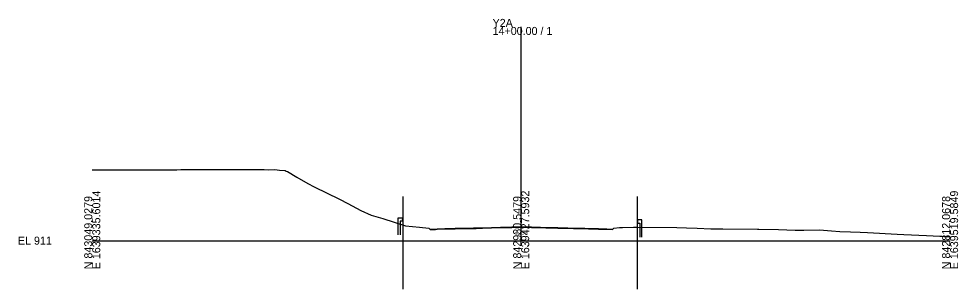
# Model space of a CAD drawing. Extents: x -26 to 303, y -10 to 10517.
# Drawn here: x -25.7 to 302.8, y 3483.1 to 3577.5 of the extents above; entities that cross this region are included whole.
import ezdxf

# ---------------------------------------------------------------- set-up
doc = ezdxf.new("R2010")
doc.units = 0
for name, color, linetype in [('Exist Cross Section Cell', 7, 'Continuous'), ('Exist XS Center Line Elevation Label', 7, 'Continuous'), ('Exist XS Ground Line', 7, 'Continuous'), ('Prop CMT Guardrail Widen Shoulder', 7, 'Continuous'), ('Prop CMT Pvmt Surface Overlay', 7, 'Continuous'), ('Scratch_Level_0', 7, 'Continuous')]:
    doc.layers.add(name, color=color, linetype=linetype)

msp = doc.modelspace()

# ---------------------------------------------------------------- linework, layer by layer
at = {"layer": 'Exist Cross Section Cell'}
for p, q in [((150, 3500), (150, 3574.66)), ((0, 3500), (150, 3500)), ((150, 3500), (300, 3500))]:
    msp.add_line(p, q, dxfattribs=at)
at = {"layer": 'Exist XS Ground Line'}
msp.add_lwpolyline([(0, 3524.72), (0.35, 3524.72), (0.66, 3524.72), (1.06, 3524.73), (2.44, 3524.73), (3.52, 3524.74), (4.22, 3524.74), (5.13, 3524.75), (6.01, 3524.75), (6.68, 3524.76), (7.61, 3524.75), (9.21, 3524.76), (9.85, 3524.76), (10.4, 3524.76), (10.81, 3524.77), (11.86, 3524.77), (13.29, 3524.77), (14.67, 3524.78), (16.18, 3524.78), (17.36, 3524.78), (19.34, 3524.79), (20.26, 3524.78), (21.44, 3524.79), (22.04, 3524.79), (22.51, 3524.79), (25.67, 3524.79), (26.22, 3524.79), (28.84, 3524.8), (29.17, 3524.8), (29.59, 3524.8), (30.95, 3524.81), (32, 3524.81), (32.95, 3524.82), (33.67, 3524.82), (35.17, 3524.82), (35.89, 3524.82), (36.72, 3524.83), (38.08, 3524.84), (38.39, 3524.84), (40.37, 3524.84), (41.5, 3524.84), (41.82, 3524.84), (44.66, 3524.83), (45.9, 3524.82), (47.83, 3524.82), (48.77, 3524.83), (49.97, 3524.81), (50.55, 3524.81), (50.99, 3524.81), (52.13, 3524.87), (54.24, 3524.85), (54.62, 3524.89), (56.85, 3524.87), (57.42, 3524.84), (60.07, 3524.85), (61.49, 3524.74), (63.8, 3524.83), (65.44, 3524.61), (67.41, 3524.57), (67.86, 3524.26), (68.27, 3524.13), (71.58, 3522.18), (75.36, 3520), (77.57, 3518.78), (86.5, 3514.55), (89.33, 3513.04), (93.88, 3510.51), (97.49, 3508.94), (101.61, 3507.76), (109.57, 3505.22), (114.47, 3504.67), (117.71, 3504.33), (118.16, 3503.85), (118.65, 3503.88), (120.03, 3503.95), (120.63, 3504), (123.35, 3504.11), (123.79, 3504.13), (125.32, 3504.16), (126.96, 3504.19), (127.43, 3504.2), (128.94, 3504.22), (130.12, 3504.25), (131.8, 3504.28), (132.2, 3504.28), (133.29, 3504.3), (134.29, 3504.31), (135.58, 3504.35), (136.07, 3504.37), (136.45, 3504.38), (139.66, 3504.44), (142.8, 3504.55), (143.73, 3504.57), (144.98, 3504.6), (145.95, 3504.63), (146.76, 3504.66), (147.81, 3504.69), (148.86, 3504.7), (149.36, 3504.7), (150, 3504.7), (152.28, 3504.68), (153.63, 3504.66), (155.44, 3504.62), (155.77, 3504.62), (156.75, 3504.59), (158.61, 3504.53), (159.23, 3504.51), (160.04, 3504.49), (161.77, 3504.44), (162.8, 3504.42), (164.12, 3504.39), (164.58, 3504.38), (164.94, 3504.37), (166.36, 3504.35), (168.28, 3504.3), (169.31, 3504.27), (171.27, 3504.22), (171.7, 3504.21), (172.27, 3504.2), (173.49, 3504.18), (174.43, 3504.14), (175.27, 3504.11), (176.34, 3504.09), (177.05, 3504.07), (177.6, 3504.06), (179.29, 3504.01), (179.97, 3503.97), (181.9, 3503.86), (182.44, 3504.35), (184.42, 3504.55), (184.73, 3504.58), (185.11, 3504.62), (185.44, 3504.63), (189.3, 3504.72), (190.3, 3504.73), (204.4, 3504.62), (207.83, 3504.47), (211.53, 3504.33), (216.29, 3504.19), (218.65, 3504.17), (220.49, 3504.16), (232.59, 3504.07), (233.16, 3504.06), (240.04, 3503.88), (245.82, 3503.68), (247.16, 3503.65), (248.9, 3503.69), (254.29, 3503.79), (258.48, 3503.42), (261.42, 3503.19), (265.21, 3503.05), (268.55, 3503.02), (271.14, 3502.89), (281.51, 3502.33), (283.8, 3502.19), (291.74, 3501.77), (296.46, 3501.54), (297.06, 3501.52), (297.82, 3501.49), (300, 3501.45)], dxfattribs=at)
at = {"layer": 'Prop CMT Guardrail Widen Shoulder'}
for points in [[(107.03, 3502.02), (107.03, 3508.02)], [(107.03, 3508.02), (108.36, 3508.02), (108.63, 3507.72)], [(108.63, 3507.14), (108.36, 3506.85), (107.69, 3506.85)], [(107.69, 3506.85), (107.69, 3502.02)], [(108.63, 3507.72), (108.36, 3507.43)], [(108.36, 3507.43), (108.63, 3507.14)], [(192.14, 3507.23), (190.81, 3507.23), (190.54, 3506.94)], [(190.54, 3506.94), (190.81, 3506.65)], [(190.81, 3506.65), (190.54, 3506.36)], [(190.54, 3506.36), (190.81, 3506.07), (191.48, 3506.07)], [(191.48, 3506.07), (191.48, 3501.23)], [(192.14, 3501.23), (192.14, 3507.23)]]:
    msp.add_lwpolyline(points, dxfattribs=at)
at = {"layer": 'Prop CMT Pvmt Surface Overlay'}
msp.add_lwpolyline([(118.04, 3503.97), (118.65, 3504), (120.02, 3504.07), (120.62, 3504.13), (123.35, 3504.24), (123.79, 3504.25), (125.31, 3504.28), (126.95, 3504.32), (127.43, 3504.32), (128.94, 3504.34), (130.12, 3504.37), (131.8, 3504.4), (132.2, 3504.41), (133.28, 3504.43), (134.29, 3504.44), (135.58, 3504.48), (136.07, 3504.49), (136.45, 3504.5), (139.65, 3504.57), (142.79, 3504.67), (143.73, 3504.69), (144.98, 3504.73), (145.94, 3504.76), (146.76, 3504.78), (147.81, 3504.81), (148.86, 3504.83), (149.36, 3504.83), (150, 3504.83), (152.28, 3504.81), (153.63, 3504.78), (155.44, 3504.75), (155.77, 3504.74), (156.76, 3504.72), (158.61, 3504.66), (159.24, 3504.64), (160.04, 3504.61), (161.77, 3504.57), (162.8, 3504.55), (164.12, 3504.51), (164.58, 3504.5), (164.94, 3504.49), (166.36, 3504.48), (168.29, 3504.42), (169.32, 3504.4), (171.27, 3504.35), (171.71, 3504.33), (172.27, 3504.32), (173.49, 3504.3), (174.44, 3504.27), (175.27, 3504.23), (176.35, 3504.21), (177.05, 3504.2), (177.6, 3504.19), (179.3, 3504.13), (179.97, 3504.1), (182.03, 3503.98)], dxfattribs=at)
at = {"layer": 'Scratch_Level_0'}
for p, q in [((108.63, 3515.38), (108.63, 3483.05)), ((190.54, 3515.38), (190.54, 3483.05)), ((108.63, 3507.72), (108.63, 3505.52)), ((190.54, 3506.94), (190.54, 3504.73))]:
    msp.add_line(p, q, dxfattribs=at)

# ---------------------------------------------------------------- texts
at = {"layer": 'Exist Cross Section Cell'}
for s, p in [('Y2A', (140, 3574.66)), ('14+00.00 / 1', (140, 3571.86)), ('EL 911', (-26, 3498.6))]:
    msp.add_text(s, height=2.8, dxfattribs=at).set_placement(p)
for s, p in [('N 843049.0279', (0, 3490)), ('E 1639335.6014', (2.8, 3490)), ('N 842930.5479', (150, 3490)), ('E 1639427.5932', (152.8, 3490)), ('N 842812.0678', (300, 3490)), ('E 1639519.5849', (302.8, 3490))]:
    msp.add_text(s, height=2.8, rotation=90, dxfattribs=at).set_placement(p)
at = {"layer": 'Exist XS Center Line Elevation Label'}
msp.add_text('915.70', height=1, dxfattribs=at).set_placement((147.91, 3502.01))

doc.saveas('drawing.dxf')
